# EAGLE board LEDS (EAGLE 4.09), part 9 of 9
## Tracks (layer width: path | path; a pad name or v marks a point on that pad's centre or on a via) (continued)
N$X.3715  (via drill 0.2)  (2 unrouted) (continued)
  Bottom 0.2: 6.97,1.73 6.42,2.28 6.08,2.28
  other vias: 6.92,1.71
N$X.3716  (via drill 0.2)  (2 unrouted)
  Top 0.8: 8.77,85.05 8.72,85 8.72,1.73
  Bottom 0.2: 8.75,1.78 8.21,2.32 7.86,2.32
  other vias: 8.71,1.76
N$Y.0  (6 unrouted)
  Bottom 0.6: 113.02,81.93 1.02,81.93 1.02,82.03
N$Y.1  (19 unrouted)
N$Y.2  (20 unrouted)
N$Y.3  (25 unrouted)
N$Y.4  (15 unrouted)
N$Y.5  (20 unrouted)
N$Y.6  (16 unrouted)
N$Y.7  (31 unrouted)
N$Y.8  (19 unrouted)
N$Y.9  (12 unrouted)
N$Y.10  (25 unrouted)
N$Y.11  (63 unrouted)
N$Y.12  (43 unrouted)
N$Y.13  (63 unrouted)
N$Y.14  (64 unrouted)
N$Y.15  (48 unrouted)
N$Y.16  (63 unrouted)
N$Y.17  (46 unrouted)
N$Y.18  (63 unrouted)
N$Y.19  (63 unrouted)
N$Y.20  (63 unrouted)
N$Y.21  (63 unrouted)
N$Y.22  (64 unrouted)
N$Y.23  (62 unrouted)
N$Y.24  (64 unrouted)
N$Y.25  (62 unrouted)
N$Y.26  (63 unrouted)
N$Y.27  (63 unrouted)
N$Y.28  (63 unrouted)
N$Y.29  (63 unrouted)
N$Y.30  (63 unrouted)
N$Y.31  (63 unrouted)
S$1
  Bottom 0.6: 113.07,79.28 1.22,79.28 1.22,79.38
S$2  (2 unrouted)
S$3  (1 unrouted)
S$4  (2 unrouted)
S$5  (1 unrouted)
S$6  (1 unrouted)
S$7  (1 unrouted)
S$8  (1 unrouted)
S$9  (4 unrouted)
S$10  (4 unrouted)
S$11  (3 unrouted)
S$12  (2 unrouted)
S$13  (4 unrouted)
S$14  (2 unrouted)
S$15  (2 unrouted)
S$16  (1 unrouted)
S$17  (2 unrouted)
S$18  (1 unrouted)
S$19  (3 unrouted)
S$20  (2 unrouted)
S$21  (1 unrouted)
S$22  (3 unrouted)
S$23
  Bottom 0.5: 114.99,45.58 114.99,45.51
S$24  (via drill 0.2)
  other vias: 14.19,33.15
S$25  (1 unrouted)
S$26  (1 unrouted)
S$27  (1 unrouted)
S$28  (1 unrouted)
S$29  (28 unrouted)
S$30  (1 unrouted)
S$31  (3 unrouted)
S$32  (2 unrouted)
S$33  (6 unrouted)
S$34  (5 unrouted)
S$35  (1 unrouted)
S$37  (9 unrouted)
S$38  (2 unrouted)
S$39  (7 unrouted)
S$40  (2 unrouted)
S$41  (7 unrouted)
S$42  (1 unrouted)
S$43  (15 unrouted)
S$44  (2 unrouted)
S$45  (1 unrouted)
S$47  (1 unrouted)
S$48  (3 unrouted)
S$49  (7 unrouted)
S$50  (6 unrouted)
S$51  (3 unrouted)
S$52  (2 unrouted)
S$53  (2 unrouted)
S$54  (1 unrouted)
S$55  (15 unrouted)
S$56  (1 unrouted)
S$57  (2 unrouted)
S$59  (8 unrouted)
S$60  (2 unrouted)
S$61  (29 unrouted)
S$62  (2 unrouted)
S$63  (27 unrouted)
S$64  (6 unrouted)
S$65  (2 unrouted)
S$66  (1 unrouted)
S$67  (4 unrouted)
S$68  (1 unrouted)
S$69  (2 unrouted)
S$70  (4 unrouted)
S$71  (3 unrouted)
S$72  (1 unrouted)
S$73  (4 unrouted)
S$75  (3 unrouted)
S$76  (2 unrouted)
S$77  (3 unrouted)
S$78  (2 unrouted)
S$79  (3 unrouted)
S$80  (4 unrouted)
S$81  (1 unrouted)
S$82  (1 unrouted)
S$83  (1 unrouted)
S$84  (1 unrouted)
S$85  (1 unrouted)
S$86  (1 unrouted)
S$87  (1 unrouted)
S$88  (1 unrouted)
S$89  (1 unrouted)
S$90  (1 unrouted)
S$91  (2 unrouted)
S$92  (1 unrouted)
S$93  (2 unrouted)
S$94  (2 unrouted)
S$95  (13 unrouted)
S$96  (1 unrouted)
S$97  (1 unrouted)
S$98  (2 unrouted)
S$99  (1 unrouted)
S$100  (10 unrouted)
S$101  (5 unrouted)
S$102  (7 unrouted)
S$103  (3 unrouted)
S$104  (6 unrouted)
S$105  (12 unrouted)
S$106  (10 unrouted)
S$107  (19 unrouted)
S$108  (9 unrouted)
S$109  (5 unrouted)
S$110  (6 unrouted)
S$111  (4 unrouted)
S$112  (2 unrouted)
S$113  (1 unrouted)
S$114  (2 unrouted)
S$115  (5 unrouted)
S$116  (2 unrouted)
S$117  (5 unrouted)
S$118  (1 unrouted)
S$119  (9 unrouted)
S$120  (7 unrouted)
S$121  (2 unrouted)
S$122  (14 unrouted)
S$123  (16 unrouted)
S$124  (9 unrouted)
S$125  (7 unrouted)
S$126  (2 unrouted)
S$127  (3 unrouted)
S$128  (5 unrouted)
S$129  (5 unrouted)
S$130  (2 unrouted)
S$131  (3 unrouted)
S$132  (2 unrouted)
S$133  (2 unrouted)
S$134  (1 unrouted)
S$135  (1 unrouted)
S$136  (1 unrouted)
S$137
  Bottom 0.5: 1.05,76.71 1.05,76.76
S$138
  Bottom 0.6: 1.07,74.19 113.17,74.23
S$139
  Bottom 0.6: 1.07,71.63 113.07,71.63
S$140
  Bottom 0.6: 1.07,69.03 113.07,69.03
S$141
  Bottom 0.6: 0.95,66.22 112.92,66.28 113.07,66.43
S$142
  Bottom 0.6: 113.07,63.88 112.89,63.58 1.04,63.58
S$143
  Bottom 0.5: 113.05,61.23 1.09,61.23 1.09,61.2
S$144
  Bottom 0.6: 0.97,58.58 113.07,58.58
S$145
  Bottom 0.6: 1.12,55.83 113.12,55.93
S$146
  Bottom 0.6: 1.07,53.13 113.07,53.13
S$147
  Bottom 0.6: 1.07,50.58 112.92,50.53
S$148
  Bottom 0.6: 112.92,47.87 1.07,47.94 1.07,48.08
S$149
  Bottom 0.6: 1.08,45.37 112.92,45.31
S$150
  Bottom 0.6: 112.8,42.74 0.94,42.94 0.97,42.93
S$151
  Bottom 0.6: 0.82,40.23 112.82,40.23
S$152
  Bottom 0.6: 0.82,37.63 112.82,37.63
S$153
  Bottom 0.6: 0.97,35.01 113.07,35.03
S$154
  Bottom 0.6: 113.07,32.43 0.97,32.39 0.97,32.33
S$155
  Bottom 0.6: 0.9,29.57 113,29.61
S$156
  Bottom 0.6: 0.93,27.1 112.94,27.14
S$157
  Bottom 0.6: 0.97,24.33 112.82,24.33
S$158
  Bottom 0.6: 0.96,21.67 112.82,21.73
S$159
  Top 0.8: 110.31,1.88 110.31,84.97
S$160
  Bottom 0.6: 113.05,16.64 0.94,16.56 0.97,16.58
S$161
  Bottom 0.6: 1.16,14.07 112.92,14.08
S$162
  Bottom 0.6: 112.92,11.53 112.92,11.39 1.17,11.38 1.17,11.54
S$163
  Bottom 0.6: 0.84,8.68 112.81,8.68
S$164
  Bottom 0.6: 114.82,6.2 0.96,6.2 0.96,6.09
S$165
  Bottom 0.5: 114.99,40.43 114.99,40.36
S$166
  Top 0.8: 82.17,1.63 82.17,84.78
S$167
  Bottom 0.5: 114.94,35.13 114.94,35.06
S$168
  Bottom 0.2: 27.71,20.47 27.36,20.47
S$169
  Bottom 0.5: 114.7,3.63 114.7,3.56 79.35,3.56 79.35,3.58 1.1,3.58
S$170
  Bottom 0.5: 114.94,29.93 114.94,29.86
S$171  (via drill 0.2)
  other vias: 101.53,41.03
S$172
  Bottom 0.5: 114.83,0.99 1.21,0.99 1.21,1.02
S$173
  Bottom 0.2: 94.64,41.03 93.84,41.82 93.84,41.86
S$174
  Bottom 0.5: 113.03,76.78 113.03,76.71 91.86,76.71 91.86,76.75 79.57,76.75 79.57,76.78 63.78,76.78 63.78,76.76 49.56,76.76 49.56,76.81 35.04,76.81 35.04,76.76 20.49,76.76 20.49,76.78 5.92,76.78 5.92,76.79 1.05,76.79
S$175  (via drill 0.2)
  other vias: 103.27,33.21
S$176
  Top 0.8: 62.81,1.43 62.81,84.83
S$177  (via drill 0.2)
  other vias: 103.25,35.8
S$178  (via drill 0.2)  (2 unrouted)
  Top 0.8: 33.49,84.99 33.98,84.5 33.98,1.68
  Bottom 0.2: 34.07,1.73 33.52,2.28 33.06,2.32
  other vias: 34.02,1.76
S$179  (via drill 0.2)
  other vias: 103.27,38.4
S$180
  Bottom 0.5: 114.94,27.23 114.94,27.16
S$181  (via drill 0.2)
  other vias: 91.06,38.44
S$182
  Bottom 0.5: 114.94,24.42 114.94,24.35
S$183  (via drill 0.2)  (1 unrouted)
  Bottom 0.2: 81.67,46.83 82.27,46.23
  Bottom 0.5: 81.47,46.83 81.67,46.83
  other vias: 82.27,46.18
S$184
  Bottom 0.5: 114.94,21.79 114.94,21.72
S$185  (via drill 0.2)  (2 unrouted)
  Bottom 0.2: 79.75,46.94 79.77,46.94 80.5,46.2
  Bottom 0.5: 79.57,46.88 79.77,46.88
  other vias: 80.52,46.18
S$186
  Bottom 0.5: 114.94,19.21 114.94,19.14
S$187  (via drill 0.2)  (2 unrouted)
  Bottom 0.2: 74.44,47 74.44,46.96 75.23,46.17
  Bottom 0.5: 74.57,46.88 74.37,46.88
  other vias: 75.27,46.18
S$188
  Bottom 0.5: 114.9,16.77 114.9,16.7
S$189  (via drill 0.2)  (2 unrouted)
  Bottom 0.2: 77.08,46.13 76.33,46.87 76.28,46.87
  Bottom 0.5: 76.17,46.88 76.32,46.88
  other vias: 77.07,46.18
S$190
  Bottom 0.5: 114.9,14.2 114.9,14.13
S$191  (via drill 0.2)  (2 unrouted)
  Bottom 0.2: 77.79,46.95 78.08,46.95 78.85,46.18
  Bottom 0.5: 77.82,46.88 78.07,46.88
  other vias: 78.7,46.2
S$192
  Bottom 0.5: 114.9,11.53 114.9,11.46
S$193
  Bottom 0.2: 65.42,41.93 65.77,41.93
S$194
  Bottom 0.5: 114.9,8.95 114.9,8.88
S$195  (via drill 0.2)
  other vias: 70.01,43.62
S$196
  Bottom 0.5: 114.85,6.32 114.85,6.25
S$197
  Bottom 0.5: 114.8,3.7 114.8,3.63
S$198
  Bottom 0.5: 114.8,1.12 114.8,1.05
S$199
  Bottom 0.6: 112.85,8.68 114.85,8.68 114.85,8.86
S$200
  Bottom 0.6: 112.89,11.37 115.03,11.37 115.03,11.41
S$201
  Bottom 0.4: 112.87,14.11 112.94,14.04 115.15,14.04
S$202
  Bottom 0.4: 112.89,16.57 112.93,16.61 115.05,16.61
S$203
  Bottom 0.4: 112.85,19.1 112.87,19.12 114.99,19.12
S$204
  Bottom 0.4: 112.85,21.65 112.89,21.61 115.12,21.61
S$205
  Bottom 0.4: 112.85,24.32 112.92,24.25 115.03,24.25
S$206
  Bottom 0.4: 112.91,27.11 112.96,27.06 114.99,27.06
S$207
  Bottom 0.4: 112.96,29.71 113.15,29.52 115.01,29.52
S$208
  Bottom 0.4: 112.91,32.42 113,32.33 114.92,32.33
S$209
  Bottom 0.4: 112.85,35.09 112.98,34.96 114.92,34.96
S$210
  Bottom 0.4: 112.87,37.63 112.94,37.56 114.96,37.56
S$211
  Bottom 0.4: 112.87,40.23 112.96,40.14 115.01,40.14
S$212
  Bottom 0.4: 112.89,42.92 113.14,42.67 114.96,42.67
S$213
  Bottom 0.4: 112.87,45.34 112.96,45.24 114.99,45.24
S$214
  Bottom 0.4: 112.89,47.75 112.91,47.78 114.96,47.78
S$215
  Bottom 0.4: 112.85,50.54 112.91,50.47 114.96,50.47
S$216
  Bottom 0.4: 113.08,53.21 113.21,53.07 114.99,53.07
S$217
  Bottom 0.4: 113.03,55.85 113.05,55.83 114.94,55.83
S$218
  Top 0.6: 35.72,84.93 35.72,84.18
S$219
  Bottom 0.5: 114.96,76.8 114.96,76.73
S$220
  Bottom 0.4: 113.05,58.57 113.1,58.52 114.96,58.52
S$221
  Bottom 0.5: 114.98,69.11 114.98,69.04
S$222
  Bottom 0.5: 114.98,61.29 114.98,61.22
S$223
  Bottom 0.5: 114.97,50.64 114.97,50.57
S$224
  Bottom 0.4: 113.05,61.15 113.08,61.12 114.96,61.12
S$225
  Bottom 0.4: 113.03,63.68 113.17,63.54 114.94,63.54
S$226
  Bottom 0.4: 113.03,66.35 113.21,66.16 114.92,66.16
S$227
  Bottom 0.4: 113.05,69.13 113.19,68.99 114.94,68.99
S$228
  Bottom 0.4: 113.03,71.62 113.05,71.59 114.94,71.59
S$229
  Bottom 0.4: 113.03,74.24 113.12,74.15 114.94,74.15
S$230
  Bottom 0.4: 113.05,76.68 114.94,76.68
S$231
  Bottom 0.4: 113.01,79.26 113.05,79.21 114.87,79.21
S$232
  Bottom 0.4: 112.98,81.88 113.03,81.84 114.87,81.84
S$300  (via drill 0.2)  (2 unrouted)
  Bottom 0.2: v73.53,46.17 72.94,46.77 72.89,46.77
  Bottom 0.5: 72.52,46.88 72.72,46.88
S$301  (via drill 0.2)  (1 unrouted)
  Bottom 0.2: 71.75,46.26 71.17,46.85 70.91,46.85
  other vias: 71.77,46.23
S$304  (via drill 0.2)  (1 unrouted)
  Bottom 0.2: 82.32,35.76 81.61,36.47 81.57,36.47
  other vias: 82.3,35.81
S$305  (via drill 0.2)  (1 unrouted)
  Bottom 0.2: 82.28,33.21 81.62,33.87 81.62,33.91
  other vias: 82.28,33.13
S$306  (via drill 0.2)  (1 unrouted)
  Bottom 0.2: 84.03,35.8 83.46,36.37 83.27,36.37
  other vias: 84.05,35.81
S$307  (via drill 0.2)  (1 unrouted)
  Bottom 0.2: 85.86,35.75 85.11,36.5 84.89,36.5
  other vias: 85.86,35.79
S$308  (via drill 0.2)  (1 unrouted)
  Bottom 0.2: 89.3,35.8 88.43,36.67 88.36,36.67
  other vias: 89.31,35.81
S$309  (via drill 0.2)  (1 unrouted)
  Bottom 0.2: 91.08,35.77 90.19,36.61 90.11,36.63
  other vias: 91.06,35.8
S$427
  Bottom 0.5: LED18.127.P$A 113.14,7.63
S$428
  Bottom 0.5: LED15.127.P$A 113.16,15.53
S$429
  Bottom 0.5: 112.92,19.16 1.14,19.16 1.14,19.05
S$516
  Bottom 0.5: LED17.127.P$A 113.16,10.23
S$518
  Bottom 0.5: LED19.127.P$A 112.82,5.03

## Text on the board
tTest: X0 | X1 | X2 | X3 | X4 | X5 | X6 | X7 | X8 | X9 | X10 | X11 | X12 | X13 | X14 | X15 | X16 | X17 | X18 | X19 | X20 | X21 | X22 | X23 | X24 | X25 | X25 | X26 | X27 | X28 | X29 | X30 | X31 | X32 | X33 | X34 | X35 | X36 | X37 | X38 | X39 | X40 | X41 | X42 | X43 | X44 | X45 | X46 | X47 | X48 | X49 | X50 | X51 | X52 | X53 | X54 | X55 | X56 | X57 | X58 | X59 | X60 | X61 | X62 | X63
